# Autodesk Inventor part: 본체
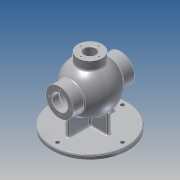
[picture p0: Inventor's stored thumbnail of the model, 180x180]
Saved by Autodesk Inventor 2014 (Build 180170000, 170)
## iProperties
Created: 2020-08
Part Number: 본체
Material: 알루미늄 6061
Document SubType Name: Modeling
Designer: kb542
Density: 2.71 g/cm^3
Appearance: 알루미늄 - 평지
Author: kb542
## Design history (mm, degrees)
sketch "스케치1"
  geometry: L1 (-53, 0)-(53, 0); A1 r 53 centre (0, 0) between (53, 0) and (-53, 0); A2 r 43 centre (0, 0) between (43, 0) and (-43, 0); 2 further points
  constraints: 4 coincident, 4 point on circle, 4 point on line, 2 centre point, 2 end point, 1 horizontal, 1 midpoint
  dimensions: "d4" = 53 radius of A1; "d5" = 43 radius of A2
revolve "회전1" sketch "스케치1" stored, may be unused: angle "d2" = 90 deg
node "작업 평면2"
sketch "스케치2"
  geometry: C1 r 85 at (0, 0); 1 further point
  constraints: 1 centre point, 1 coincident
  dimensions: "d7" = 170 diameter of C1
extrude "돌출1" join sketch "스케치2" distance "d8" = 10; taper "d9" = 0 deg
node "작업 평면3"
sketch "스케치3"
  geometry: C1 r 31 at (0, 0); 1 further point
  constraints: 1 centre point, 1 coincident
  dimensions: "d11" = 62 diameter of C1
extrude "돌출2" join sketch "스케치3" stored distance "d12" = 10; taper "d13" = 0 deg
sketch "스케치4"
  geometry: C1 r 31 at (0, 0) reference; C2 r 17.5 at (0, 0)
  constraints: 1 centre point, 1 coincident
  dimensions: "d14" = 35 diameter of C2
extrude "돌출3" cut sketch "스케치4" distance "d15" = 16; taper "d16" = 0 deg
sketch "스케치5"
  geometry: C1 r 17.5 at (0, 0) reference; C2 r 18.5 at (0, 0)
  constraints: 1 centre point, 1 coincident
  dimensions: "d17" = 37 diameter of C2
extrude "돌출4" cut sketch "스케치5" distance "d18" = 1.75; taper "d19" = 0 deg
sketch "스케치6"
  geometry: C1 r 31 at (0, 0) reference; C2 r 17.5 at (0, 0)
  constraints: 1 centre point, 1 coincident
  dimensions: "d20" = 35 diameter of C2
extrude "돌출5" cut sketch "스케치6" stored distance "d21" = 1.75; taper "d22" = 0 deg
sketch "스케치7"
  geometry: C1 r 17.5 at (0, 0) reference; 1 further point
  constraints: 1 vertical alignment
  dimensions: "d23" = 24 distance of point (0, 24) C1.centre
hole "구멍1" sketch "스케치7" at (0, 24) diameter "d24" = 3.242; stored, may be unused: countersink angle "d28" = 90 deg, drill point angle "d30" = 118 deg; dims "d25" = 12, "d26" = 4, "d27" = 2, "d29" = 15
node "작업 평면4"
sketch "스케치8"
  geometry: C1 r 27 at (0, 0); 1 further point
  constraints: 1 centre point, 1 coincident
  dimensions: "d35" = 54 diameter of C1
extrude "돌출6" join sketch "스케치8" stored distance "d36" = 1.75; taper "d37" = 0 deg
sketch "스케치9"
  geometry: C1 r 27 at (0, 0) reference; C2 r 13 at (0, 0)
  constraints: 1 centre point, 1 coincident
  dimensions: "d38" = 26 diameter of C2
extrude "돌출7" cut sketch "스케치9" stored distance "d39" = 1.75; taper "d40" = 0 deg
chamfer "모따기1" distance "d41" = 1; stored, may be unused: second distance "d42" = 2, angle "d43" = 45 deg
sketch "스케치10"
  geometry: C1 r 27 at (0, 0) reference; 1 further point
  constraints: 1 vertical alignment
  dimensions: "d44" = 20 distance of point (0, 20) C1.centre
hole "구멍2" sketch "스케치10" at (0, 20) diameter "d45" = 3.242; stored, may be unused: countersink angle "d49" = 90 deg, drill point angle "d51" = 118 deg; dims "d46" = 12, "d47" = 4, "d48" = 2, "d50" = 15
sketch "스케치11"
  geometry: L1 (-4, -52)-(4, -52); L2 (4, -52)-(4, 52); L3 (4, 52)-(-4, 52); L4 (-4, 52)-(-4, -52); L5 (-4, -52)-(4, 52); L6 (4, -52)-(-4, 52); C1 r 85 at (0, 0) reference
  constraints: 12 end point, 2 midpoint, 2 parallel, 1 horizontal, 1 perpendicular
  dimensions: "d55" = 104 distance of L1.end L2.end; "d56" = 8 distance of L2.end L3.end
extrude "돌출8" join sketch "스케치11" stored distance "d57" = 1.75; taper "d58" = 0 deg
sketch "스케치12"
  geometry: L1 (43, -4)-(-43, -4); L2 (-43, -4)-(-43, 4); L3 (-43, 4)-(43, 4); L4 (43, 4)-(43, -4); L5 (43, -4)-(-43, 4); L6 (-43, -4)-(43, 4); C1 r 85 at (0, 0) reference
  constraints: 12 end point, 2 midpoint, 2 parallel, 1 horizontal, 1 perpendicular
  dimensions: "d59" = 86 distance of L2.end L3.end; "d60" = 8 distance of L1.end L2.end
extrude "돌출9" join sketch "스케치12" stored distance "d61" = 1.75; taper "d62" = 0 deg
node "작업 평면5"
sketch "스케치13"
  geometry: L1 (-27, 65)-(27, 65) reference; L2 (-27, 65)-(-27, 45.607) reference; 2 further points
  constraints: 1 other
  dimensions: "d64" = 9 distance from line of L1 point (0, 56); "d65" = 27 distance from line of point (0, 56) L2
feature "엠보싱1" sketch "스케치13" dims "d66" = 0.5, "d67" = 0
sketch "스케치14"
  geometry: C1 r 85 at (0, 0) reference; 1 further point
  constraints: 1 vertical alignment
  dimensions: "d68" = 72.5 distance of point (0, 72.5) C1.centre
hole "구멍3" sketch "스케치14" at (0, 72.5) diameter "d69" = 9; stored, may be unused: countersink angle "d73" = 90 deg, drill point angle "d75" = 118 deg; dims "d70" = 12, "d71" = 4, "d72" = 2, "d74" = 15
fillet "모깎기1" dims "d79" = 3
fillet "모깎기2" dims "d80" = 3
fillet "모깎기3" dims "d81" = 3
node "솔리드1"
mirror "대칭1"
pattern_circular "원형 패턴1" dims angle "d32" = 360 deg
mirror "대칭2"
pattern_circular "원형 패턴2" dims angle "d53" = 360 deg
pattern_circular "원형 패턴3" dims angle "d77" = 360 deg
other parameters: "d6" = -85, "d10" = -68, "d63" = -103
